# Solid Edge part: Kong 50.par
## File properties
Title: Kong 50 50x38 Cm
Author: DESYS
Template: Normal.par
Last saved by: s.pallini
Revision: 9
Application: Solid Edge
Tipo di contenuto documento: 0
Precisione: 0,990
Document Number: 8051
Revision: 0
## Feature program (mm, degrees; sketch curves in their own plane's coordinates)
thicken "Assegnare_spessore_2"  Distance1 = 10 mm
thicken "Assegnare_spessore_1"  Distance1 = 10 mm
fillet "Rotondo_1" radius 30
fillet "Rotondo_2" radius 5
fillet "Rotondo_3" radius 5
sketch for "unnamed Cutout 1" plane through (0, 0, 0) normal (0, 0, 1) x-axis (1, 0, 0)
  circle centre (0, 0) radius 25
extrude "unnamed Cutout 1" cut through
sketch for "ProtrusioneEstrusa_1" plane through (0, 0, 15) normal (0, 0, 1) x-axis (1, 0, 0)
extrude "ProtrusioneEstrusa_1" add  Profile_Plane1_Distance = 15 mm
fillet "Rotondo_4" radius 10
sketch for "ExtrudedCutout_2" #1 plane through (0.4335, 0, 15) normal (0, 0, -1) x-axis (0, -1, 0)
sketch for "ExtrudedCutout_2" #2 plane through (0.4335, 0, 15) normal (0, 0, -1) x-axis (0, -1, 0)
sketch for "ExtrudedCutout_2" #3 plane through (0.4335, 0, 15) normal (0, 0, -1) x-axis (0, -1, 0)
extrude "ExtrudedCutout_2" cut finite 15 along -normal
fillet "Rotondo_5" radius 5
Other named dimensions: "CurveByTable_2": Tolerance = 1 mm | "CurveByTable_3": Tolerance = 1 mm | "CurveByTable_4": Tolerance = 1 mm
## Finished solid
Body 1: solid body, 30 faces, 53 edges, 24 vertices.
  Faces by surface: blend 20, plane 3, cylinder 2, swept 2, offset 1, spline 1, torus 1
  Edges by curve: intersection 32, circle 20, ellipse 1
Body 2: sheet body, 1 face, 4 edges, 4 vertices.
  Faces by surface: spline 1
  Edges by curve: spline 4
Bounding box of the edges (mm; curved faces can reach further): 395.512 x 505.000 x 140.000, from (-184.853, -240, 15) to (210.6595, 265, 155).
Cylindrical faces by radius (mm): R25 x1, R35 x1
Toroidal faces (ring radius, tube radius in mm): R30 r5 x1
Planar faces by outward normal: -z 3
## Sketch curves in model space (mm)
arc centre (-4.1484, 0, 307.5549) radius 287.5849 from (-180, 0, 80) through (23.028, 0, 21.257) to (200, 0, 105)
circle centre (0, 0, 20) radius 25
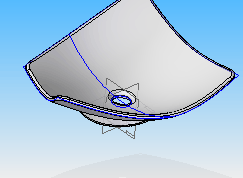
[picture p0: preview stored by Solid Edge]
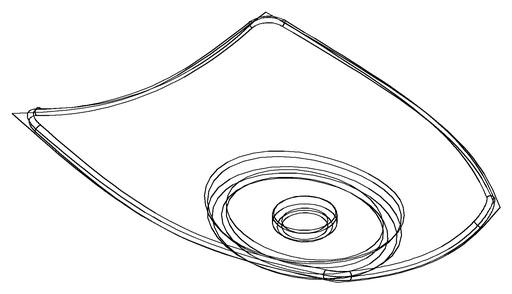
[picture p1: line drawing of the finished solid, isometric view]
